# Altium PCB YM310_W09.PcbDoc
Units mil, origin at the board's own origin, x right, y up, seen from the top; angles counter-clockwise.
Board outline 6000 x 4000 mil, 4 copper layers (Top, 内层 2, 内层 3, Bottom), stack 35.4 mil thick; 1 components, 0 nets, 109 pads, 0 vias.
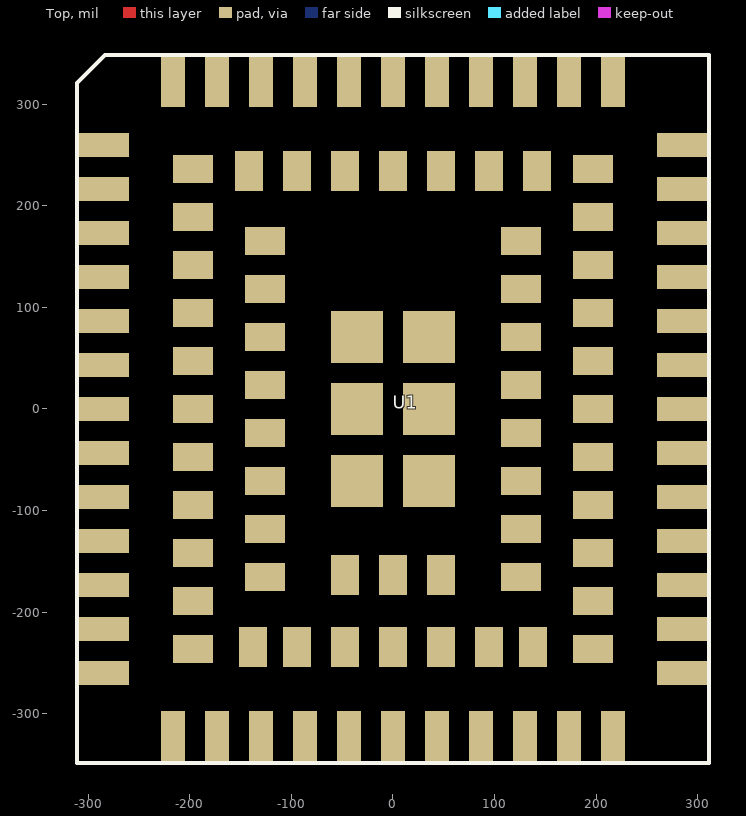
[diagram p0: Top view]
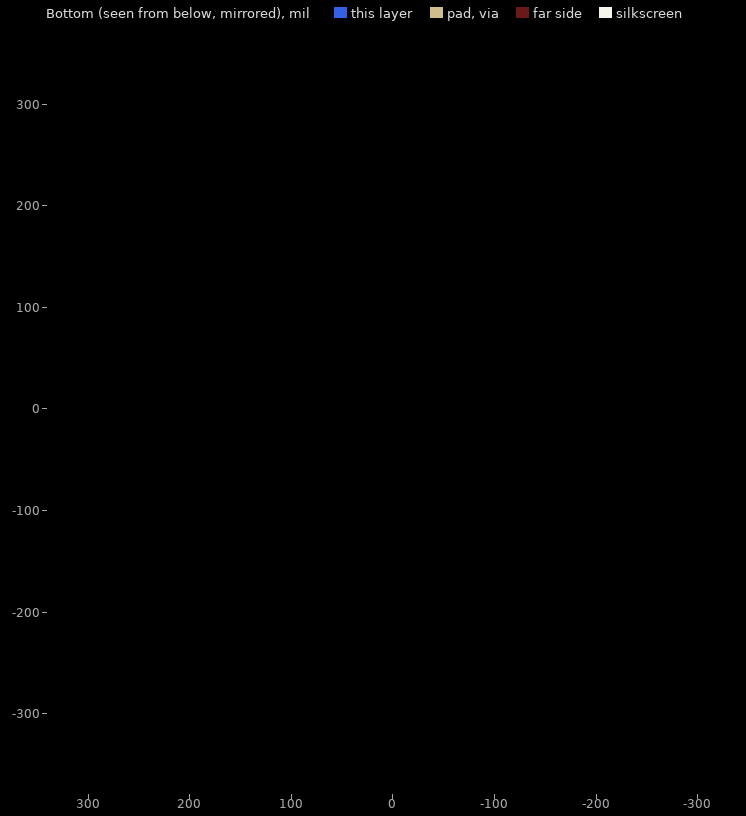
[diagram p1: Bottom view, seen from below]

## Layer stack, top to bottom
Solder Mask Top: solder mask 0.4, Solder Resist, Dk 3.5
Top: signal copper 1.35
Dielectric 1: dielectric 10, FR-4, Dk 4.3
内层 2: signal copper 1.35
Dielectric2: dielectric 10, FR-4, Dk 4.3
内层 3: signal copper 1.35
Dielectric3: dielectric 10, FR-4, Dk 4.3
Bottom: signal copper 1.35
Solder Mask Bottom: solder mask 0.4, Solder Resist, Dk 3.5

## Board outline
-9000,-9000 -3000,-9000 -3000,-5000 -9000,-5000

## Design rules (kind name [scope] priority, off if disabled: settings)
Clearance "Clearance - Default - DEFAULT- SMD" [IsVia vs IsSMTPin] p1: gap=6
Clearance "Clearance - Default - DEFAULT - Via" [IsVia vs IsVia] p2: gap=6
Clearance "Clearance - Default - DEFAULT - Net" [All] p3: gap=6 except(10: Text-Text)
ComponentClearance "ComponentClearance - Default - DEFAULT" [All] p1: gap=6 collisioncheckmode=3 verticalgap=10 showdistances=FALSE
FanoutControl Fanout_Small [(CompPinCount < 5)] p3: bgadir=Out bgaviamode=Centered fanoutstyle=Auto fanoutdirection=OutThenIn viagrid=1 // Fanout_Small (Default Rule)
FanoutControl Fanout_SOIC [IsSOIC] p4: bgadir=Out bgaviamode=Centered fanoutstyle=Auto fanoutdirection=Alternating viagrid=1 // Fanout_SOIC (Default Rule)
HoleToHoleClearance "HoleToHoleClearance - Default - DEFAULT" [All] p1: gap=6 allowstackedmicrovias=TRUE
Length "Default Length" [All] p1: maxlimit=50000 minlimit=0
MaxMinImpedance "Default Impedance" [All] p1: minimum=50.00 maximum=150.0
ParallelSegment "Default Parallel Segment Adjasent" [All] p1: limit=1000 gap=200
ParallelSegment "Default Parallel Segment Same Layer" [All] p2: limit=1000 gap=200
PlaneConnect "Default PlaneConnect" [All] p1: planeconnectstyle=Relief reliefexpansion=20 reliefentries=0 reliefconductorwidth=15 reliefairgap=10
PolygonConnect "PolygonConnect - Default SMT" [IsSMTPin] p1: connectstyle=Relief reliefconductorwidth=10 reliefentries=4 polygonreliefangle="45 Angle" airgapwidth=10
PolygonConnect "PolygonConnect - Default Pad" [All] p2: connectstyle=Relief reliefconductorwidth=15 reliefentries=4 polygonreliefangle="45 Angle" airgapwidth=10
RoutingLayers "RoutingLayers - Default - DEFAULT" [All] p1: top layer_v5=TRUE mid layer 1_v5=TRUE mid layer 2_v5=TRUE bottom layer_v5=TRUE
RoutingPriority "RoutingPriority - Default - DEFAULT" [All] p1: routingpriority=3
RoutingTopology "Default Routing Topology" [All] p1: topology=Shortest
RoutingVias "RoutingVias - Default - DEFAULT" [All] p1: holewidth=37 width=55 viastyle="Through Hole" minholewidth=37 minwidth=55 maxholewidth=37 maxwidth=55
SMDToCorner "SMDToCorner - Default - DEFAULT" [All] p1: distance=60000
SolderMaskExpansion [All] p1: expansion=4
Width "Default Width" [All] p1: maxlimit=12 minlimit=12 preferedwidth=12
20 further rules are at their usual default settings.

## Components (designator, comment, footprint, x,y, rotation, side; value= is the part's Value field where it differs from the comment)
U1 "AIR800E" AIR800E 0,0 r0 top

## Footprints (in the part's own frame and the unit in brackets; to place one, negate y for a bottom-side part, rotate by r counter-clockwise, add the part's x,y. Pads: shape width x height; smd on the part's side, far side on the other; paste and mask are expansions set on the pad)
AIR800E [mm]
  rect 1.3x0.6 smd paste+0.05 mask+0.05: 1(-7.25,6.6) 2(-7.25,5.5) 3(-7.25,4.4) 4(-7.25,3.3) 5(-7.25,2.2) 6(-7.25,1.1) 7(-7.25,0) 8(-7.25,-1.1) 9(-7.25,-2.2) 10(-7.25,-3.3) 11(-7.25,-4.4) 12(-7.25,-5.5) 13(-7.25,-6.6) 23(7.25,-6.6) 24(7.25,-5.5) 25(7.25,-4.4) 26(7.25,-3.3) 27(7.25,-2.2) 28(7.25,-1.1) 29(7.25,0) 30(7.25,1.1) 31(7.25,2.2) 32(7.25,3.3) 33(7.25,4.4) 34(7.25,5.5) 35(7.25,6.6)
  rect 0.6x1.3 smd paste+0.05 mask+0.05: 14(-4.4,-8.2) 15(-3.3,-8.2) 16(-2.2,-8.2) 17(-1.1,-8.2) 18(0,-8.2) 19(1.1,-8.2) 20(2.2,-8.2) 21(3.3,-8.2) 22(4.4,-8.2) 36(4.4,8.2) 37(3.3,8.2) 38(2.2,8.2) 39(1.1,8.2) 40(0,8.2) 41(-1.1,8.2) 42(-2.2,8.2) 43(-3.3,8.2) 44(-4.4,8.2) 95(-5.5,-8.2) 96(5.5,-8.2) 97(5.5,8.2) 98(-5.5,8.2)
  rect 1x0.7 smd mask+0.05: 45(-5,4.8) 46(-5,3.6) 47(-5,2.4) 48(-5,1.2) 49(-5,0) 50(-5,-1.2) 51(-5,-2.4) 52(-5,-3.6) 53(-5,-4.8) 59(5,-4.8) 60(5,-3.6) 61(5,-2.4) 62(5,-1.2) 63(5,0) 64(5,1.2) 65(5,2.4) 66(5,3.6) 67(5,4.8) 73(-3.2,4.2) 74(-3.2,3) 75(-3.2,1.8) 76(-3.2,0.6) 77(-3.2,-0.6) 78(-3.2,-1.8) 79(-3.2,-3) 80(-3.2,-4.2) 81(3.2,-4.2) 82(3.2,-3) 83(3.2,-1.8) 84(3.2,-0.6) 85(3.2,0.6) 86(3.2,1.8) 87(3.2,3) 88(3.2,4.2) 99(-5,6) 100(-5,-6) 103(5,-6) 104(5,6)
  rect 0.7x1 smd mask+0.05: 54(-2.4,-5.95) 55(-1.2,-5.95) 56(0,-5.95) 57(1.2,-5.95) 58(2.4,-5.95) 68(2.4,5.95) 69(1.2,5.95) 70(0,5.95) 71(-1.2,5.95) 72(-2.4,5.95) 101(-3.5,-5.95) 102(3.5,-5.95) 105(3.6,5.95) 106(-3.6,5.95) 107(-1.2,-4.15) 108(0,-4.15) 109(1.2,-4.15)
  rect 1.3x1.3 smd mask+0.05: 89(-0.9,1.8) 90(-0.9,0) 91(-0.9,-1.8) 92(0.9,-1.8) 93(0.9,0) 94(0.9,1.8)
  silkscreen extent -7.9,-8.85 7.9,8.85

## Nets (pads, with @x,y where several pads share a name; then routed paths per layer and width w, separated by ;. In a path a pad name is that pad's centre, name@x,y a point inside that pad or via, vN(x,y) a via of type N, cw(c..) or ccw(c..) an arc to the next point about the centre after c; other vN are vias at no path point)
pads on no net: U1.1 U1.2 U1.3 U1.4 U1.5 U1.6 U1.7 U1.8 U1.9 U1.10 U1.11 U1.12 U1.13 U1.14 U1.15 U1.16 U1.17 U1.18 U1.19 U1.20 U1.21 U1.22 U1.23 U1.24 U1.25 U1.26 U1.27 U1.28 U1.29 U1.30 U1.31 U1.32 U1.33 U1.34 U1.35 U1.36 U1.37 U1.38 U1.39 U1.40 U1.41 U1.42 U1.43 U1.44 U1.45 U1.46 U1.47 U1.48 U1.49 U1.50 U1.51 U1.52 U1.53 U1.54 U1.55 U1.56 U1.57 U1.58 U1.59 U1.60 U1.61 U1.62 U1.63 U1.64 U1.65 U1.66 U1.67 U1.68 U1.69 U1.70 U1.71 U1.72 U1.73 U1.74 U1.75 U1.76 U1.77 U1.78 U1.79 U1.80 U1.81 U1.82 U1.83 U1.84 U1.85 U1.86 U1.87 U1.88 U1.89 U1.90 U1.91 U1.92 U1.93 U1.94 U1.95 U1.96 U1.97 U1.98 U1.99 U1.100 U1.101 U1.102 U1.103 U1.104 U1.105 U1.106 U1.107 U1.108 U1.109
